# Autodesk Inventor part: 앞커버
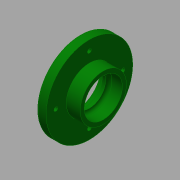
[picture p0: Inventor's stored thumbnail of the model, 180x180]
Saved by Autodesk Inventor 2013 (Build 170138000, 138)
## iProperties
Created: 2015-09
Part Number: 앞커버
Material: 알루미늄 6061
Document SubType Name: Modeling
Designer: mduedu
Density: 2.71 g/cm^3
Mass: 58.9874 g
Surface Area: 98.7754 cm^2
Volume: 21.7666 cm^3
Author: mduedu
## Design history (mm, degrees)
sketch "스케치1"
  geometry: L1 (-4, 67)-(-16, 67); L2 (-16, 67)-(-16, 84.5); L3 (-16, 84.5)-(-24, 84.5); L4 (-24, 84.5)-(-24, 70.5); L5 (-27, 70.5)-(-27, 61); L6 (-27, 61)-(-4, 61); L7 (-4, 61)-(-4, 67); L8 (-79.5, 39.5)-(-79.5, 54.5) reference; L9 (48.5, 54.5)-(48.5, 39.5) reference; L10 (-79.5, 47)-(48.5, 47); L11 (-24, 70.5)-(-27, 70.5); 3 further points
  constraints: 18 end point, 6 parallel, 4 midpoint, 1 horizontal, 1 perpendicular, 1 vertical alignment
  dimensions: "d0" = 23 distance between parallel lines of L7 L5; "d2" = 28 diameter of L6 L10; "d3" = 40 diameter of L1 L10; "d5" = 12 distance of L1.start L1.end; "d6" = 75 diameter of L3 L10; "d7" = 8 distance of L2.end L3.end; "d8" = 47 diameter of L4.end L10
revolve "회전1" sketch "스케치1" stored, may be unused: angle "d4" = 90 deg
sketch "스케치2"
  geometry: C1 r 37.5 at (0, 0) reference; 2 further points
  constraints: 1 coincident
hole "구멍1" sketch "스케치2" at (0, 0) diameter "d11" = 33; stored, may be unused: countersink angle "d15" = 90 deg, drill point angle "d17" = 0 deg; dims "d12" = 6, "d13" = 4, "d14" = 2, "d16" = 12
fillet "모깎기1" dims "d18" = 3
fillet "모깎기2" dims "d19" = 1
sketch "스케치3"
  geometry: C1 r 37.5 at (0, 0) reference; 2 further points
  constraints: 1 coincident
hole "구멍2" sketch "스케치3" at (0, 0) diameter "d20" = 40; stored, may be unused: countersink angle "d24" = 90 deg, drill point angle "d26" = 0 deg; dims "d21" = 6, "d22" = 4, "d23" = 2, "d25" = 8
fillet "모깎기3" dims "d27" = 0.4
chamfer "모따기1" distance "d28" = 1; stored, may be unused: second distance "d29" = 2, angle "d30" = 30 deg
sketch "스케치7" dims "d56" = 58
  geometry: C1 r 37.5 at (0, 0) reference; 5 further points
  constraints: 2 vertical alignment, 1 coincident, 7 other
  dimensions: "d59" = 360 deg dimension on C1.centre point (0, 29) (derived)
hole "구멍4" sketch "스케치7" at (0, 29), (-29, 0), (0, -29), (29, 0) diameter "d48" = 3.4; stored, may be unused: countersink angle "d52" = 90 deg, drill point angle "d54" = 0 deg; dims "d49" = 6, "d50" = 6.5, "d51" = 3.4, "d53" = 8
node "솔리드1"
node "참조1"
node "참조2"
